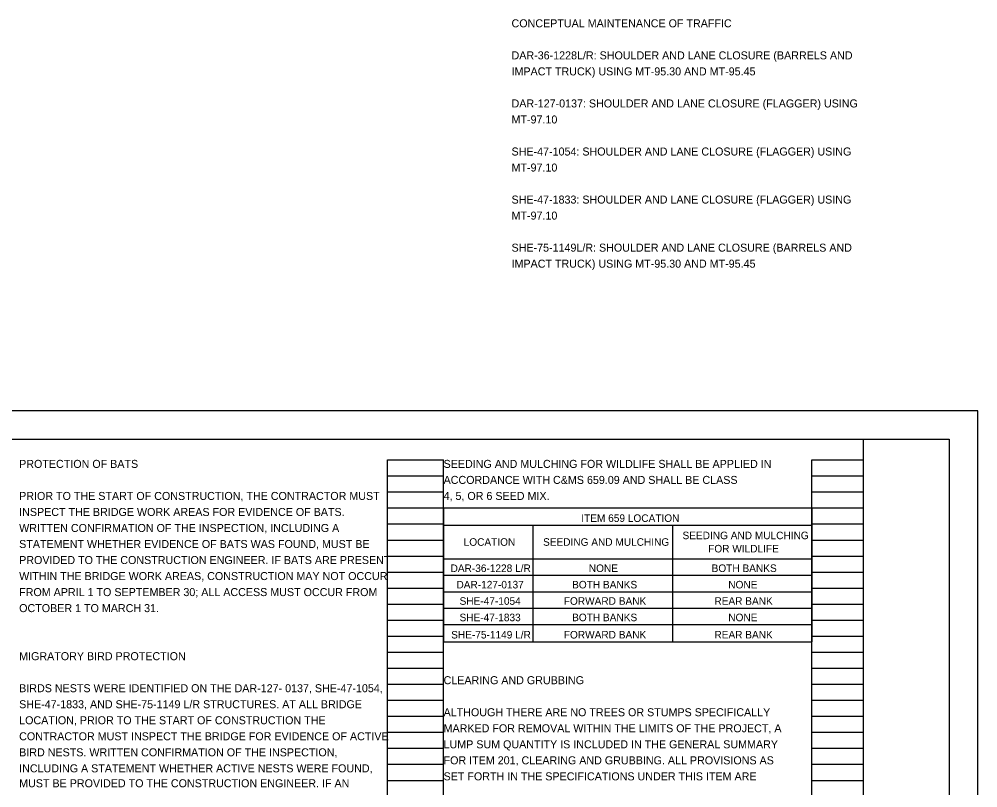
# Model space of a CAD drawing. Extents: x 0 to 66.4, y 0 to 28.8.
# Drawn here: x 17.24 to 34, y 15.41 to 28.84 of the extents above; entities that cross this region are included whole.
import ezdxf

# ---------------------------------------------------------------- set-up
doc = ezdxf.new("R2010")
doc.units = 0
for name, color, linetype in [('Default', 7, 'Continuous'), ('SH_Border', 7, 'Continuous'), ('SH_Cut_Line', 7, 'Continuous'), ('SH_Data', 7, 'Continuous'), ('SH_Text', 7, 'Continuous')]:
    doc.layers.add(name, color=color, linetype=linetype)

msp = doc.modelspace()

# ---------------------------------------------------------------- linework, layer by layer
at = {"layer": 'Default'}
for p, q in [((24.66, 20.3), (31.1, 20.3)), ((24.66, 20.3), (24.66, 17.962)), ((31.1, 20.3), (31.1, 17.962)), ((24.66, 19.999), (31.1, 19.999)), ((26.223, 19.999), (26.223, 17.962)), ((28.662, 19.999), (28.662, 17.962)), ((24.66, 19.411), (31.1, 19.411)), ((24.66, 19.124), (31.1, 19.124)), ((24.66, 18.837), (31.1, 18.837)), ((24.66, 18.55), (31.1, 18.55)), ((24.66, 18.263), (31.1, 18.263)), ((24.66, 17.962), (31.1, 17.962))]:
    msp.add_line(p, q, dxfattribs=at)
at = {"layer": 'SH_Border'}
msp.add_line((32, 0.5), (32, 21.5), dxfattribs=at)
msp.add_lwpolyline([(1.5, 21.5), (33.5, 21.5), (33.5, 0.5), (1.5, 0.5)], close=True, dxfattribs=at)
at = {"layer": 'SH_Cut_Line'}
msp.add_lwpolyline([(0, 0), (34, 0), (34, 22), (0, 22)], close=True, dxfattribs=at)
at = {"layer": 'SH_Data'}
for p, q in [((23.68, 0.98), (23.68, 21.14)), ((23.68, 21.14), (24.66, 21.14)), ((24.66, 0.98), (24.66, 21.14)), ((31.1, 0.98), (31.1, 21.14)), ((31.1, 21.14), (32, 21.14)), ((32, 0.98), (32, 21.14)), ((23.68, 20.86), (24.66, 20.86)), ((31.1, 20.86), (32, 20.86)), ((23.68, 20.58), (24.66, 20.58)), ((31.1, 20.58), (32, 20.58)), ((23.68, 20.3), (24.66, 20.3)), ((31.1, 20.3), (32, 20.3)), ((23.68, 20.02), (24.66, 20.02)), ((31.1, 20.02), (32, 20.02)), ((23.68, 19.74), (24.66, 19.74)), ((31.1, 19.74), (32, 19.74)), ((23.68, 19.46), (24.66, 19.46)), ((31.1, 19.46), (32, 19.46)), ((23.68, 19.18), (24.66, 19.18)), ((31.1, 19.18), (32, 19.18)), ((23.68, 18.9), (24.66, 18.9)), ((31.1, 18.9), (32, 18.9)), ((23.68, 18.62), (24.66, 18.62)), ((31.1, 18.62), (32, 18.62)), ((23.68, 18.34), (24.66, 18.34)), ((31.1, 18.34), (32, 18.34)), ((23.68, 18.06), (24.66, 18.06)), ((31.1, 18.06), (32, 18.06)), ((23.68, 17.78), (24.66, 17.78)), ((31.1, 17.78), (32, 17.78)), ((23.68, 17.5), (24.66, 17.5)), ((31.1, 17.5), (32, 17.5)), ((23.68, 17.22), (24.66, 17.22)), ((31.1, 17.22), (32, 17.22)), ((23.68, 16.94), (24.66, 16.94)), ((31.1, 16.94), (32, 16.94)), ((23.68, 16.66), (24.66, 16.66)), ((31.1, 16.66), (32, 16.66)), ((23.68, 16.38), (24.66, 16.38)), ((31.1, 16.38), (32, 16.38)), ((23.68, 16.1), (24.66, 16.1)), ((31.1, 16.1), (32, 16.1)), ((23.68, 15.82), (24.66, 15.82)), ((31.1, 15.82), (32, 15.82)), ((23.68, 15.54), (24.66, 15.54)), ((31.1, 15.54), (32, 15.54))]:
    msp.add_line(p, q, dxfattribs=at)

# ---------------------------------------------------------------- texts
at = {"layer": 'Default'}
for s, height, p in [('ITEM 659 LOCATION', 0.13196, (27.067, 20.056)), ('SEEDING AND MULCHING ', 0.13196, (28.837, 19.754)), ('LOCATION', 0.132, (25.011, 19.639)), ('SEEDING AND MULCHING', 0.13196, (26.399, 19.639)), ('FOR WILDLIFE', 0.13196, (29.286, 19.523)), ('DAR-36-1228 L/R', 0.13196, (24.782, 19.181)), ('NONE', 0.132, (27.199, 19.181)), ('BOTH BANKS', 0.132, (29.346, 19.181)), ('DAR-127-0137', 0.13196, (24.885, 18.894)), ('BOTH BANKS', 0.132, (26.907, 18.894)), ('NONE', 0.132, (29.637, 18.894)), ('SHE-47-1054', 0.13196, (24.94, 18.608)), ('FORWARD BANK', 0.13196, (26.762, 18.608)), ('REAR BANK', 0.132, (29.395, 18.608)), ('SHE-47-1833', 0.13196, (24.939, 18.321)), ('BOTH BANKS', 0.132, (26.907, 18.321)), ('NONE', 0.132, (29.637, 18.321)), ('SHE-75-1149 L/R', 0.13196, (24.793, 18.019)), ('FORWARD BANK', 0.13196, (26.762, 18.019)), ('REAR BANK', 0.132, (29.395, 18.019))]:
    msp.add_text(s, height=height, dxfattribs=at).set_placement(p)
at = {"layer": 'SH_Text'}
for s, p in [('CONCEPTUAL MAINTENANCE OF TRAFFIC', (25.848, 28.699)), ('DAR-36-1228L/R: SHOULDER AND LANE CLOSURE (BARRELS AND ', (25.848, 28.139)), ('IMPACT TRUCK) USING MT-95.30 AND MT-95.45', (25.848, 27.859)), ('DAR-127-0137: SHOULDER AND LANE CLOSURE (FLAGGER) USING', (25.848, 27.299)), ('MT-97.10', (25.848, 27.019)), ('SHE-47-1054: SHOULDER AND LANE CLOSURE (FLAGGER) USING', (25.848, 26.459)), ('MT-97.10', (25.848, 26.179)), ('SHE-47-1833: SHOULDER AND LANE CLOSURE (FLAGGER) USING', (25.848, 25.619)), ('MT-97.10', (25.848, 25.339)), ('SHE-75-1149L/R: SHOULDER AND LANE CLOSURE (BARRELS AND ', (25.848, 24.779)), ('IMPACT TRUCK) USING MT-95.30 AND MT-95.45', (25.848, 24.499)), ('PROTECTION OF BATS', (17.24, 21)), ('SEEDING AND MULCHING FOR WILDLIFE SHALL BE APPLIED IN ', (24.66, 21)), ('ACCORDANCE WITH C&MS 659.09 AND SHALL BE CLASS ', (24.66, 20.72)), ('PRIOR TO THE START OF CONSTRUCTION, THE CONTRACTOR MUST', (17.24, 20.44)), ('4, 5, OR 6 SEED MIX. ', (24.66, 20.44)), ('INSPECT THE BRIDGE WORK AREAS FOR EVIDENCE OF BATS.', (17.24, 20.16)), ('WRITTEN CONFIRMATION OF THE INSPECTION, INCLUDING A', (17.24, 19.88)), ('STATEMENT WHETHER EVIDENCE OF BATS WAS FOUND, MUST BE', (17.24, 19.6)), ('PROVIDED TO THE CONSTRUCTION ENGINEER. IF BATS ARE PRESENT', (17.24, 19.32)), ('WITHIN THE BRIDGE WORK AREAS, CONSTRUCTION MAY NOT OCCUR', (17.24, 19.04)), ('FROM APRIL 1 TO SEPTEMBER 30; ALL ACCESS MUST OCCUR FROM', (17.24, 18.76)), ('OCTOBER 1 TO MARCH 31.', (17.24, 18.48)), ('MIGRATORY BIRD PROTECTION', (17.24, 17.64)), ('CLEARING AND GRUBBING', (24.66, 17.22)), ('BIRDS NESTS WERE IDENTIFIED ON THE DAR-127- 0137, SHE-47-1054,', (17.24, 17.08)), ('SHE-47-1833, AND SHE-75-1149 L/R STRUCTURES. AT ALL BRIDGE', (17.24, 16.8)), ('ALTHOUGH THERE ARE NO TREES OR STUMPS SPECIFICALLY', (24.66, 16.66)), ('LOCATION, PRIOR TO THE START OF CONSTRUCTION THE', (17.24, 16.52)), ('MARKED FOR REMOVAL WITHIN THE LIMITS OF THE PROJECT, A', (24.66, 16.38)), ('CONTRACTOR MUST INSPECT THE BRIDGE FOR EVIDENCE OF ACTIVE', (17.24, 16.24)), ('BIRD NESTS. WRITTEN CONFIRMATION OF THE INSPECTION,', (17.24, 15.96)), ('LUMP SUM QUANTITY IS INCLUDED IN THE GENERAL SUMMARY', (24.66, 16.1)), ('FOR ITEM 201, CLEARING AND GRUBBING. ALL PROVISIONS AS', (24.66, 15.82)), ('INCLUDING A STATEMENT WHETHER ACTIVE NESTS WERE FOUND,', (17.24, 15.68)), ('SET FORTH IN THE SPECIFICATIONS UNDER THIS ITEM ARE', (24.66, 15.54)), ('MUST BE PROVIDED TO THE CONSTRUCTION ENGINEER. IF AN', (17.24, 15.419))]:
    msp.add_text(s, height=0.14, dxfattribs=at).set_placement(p)

doc.saveas('drawing.dxf')
